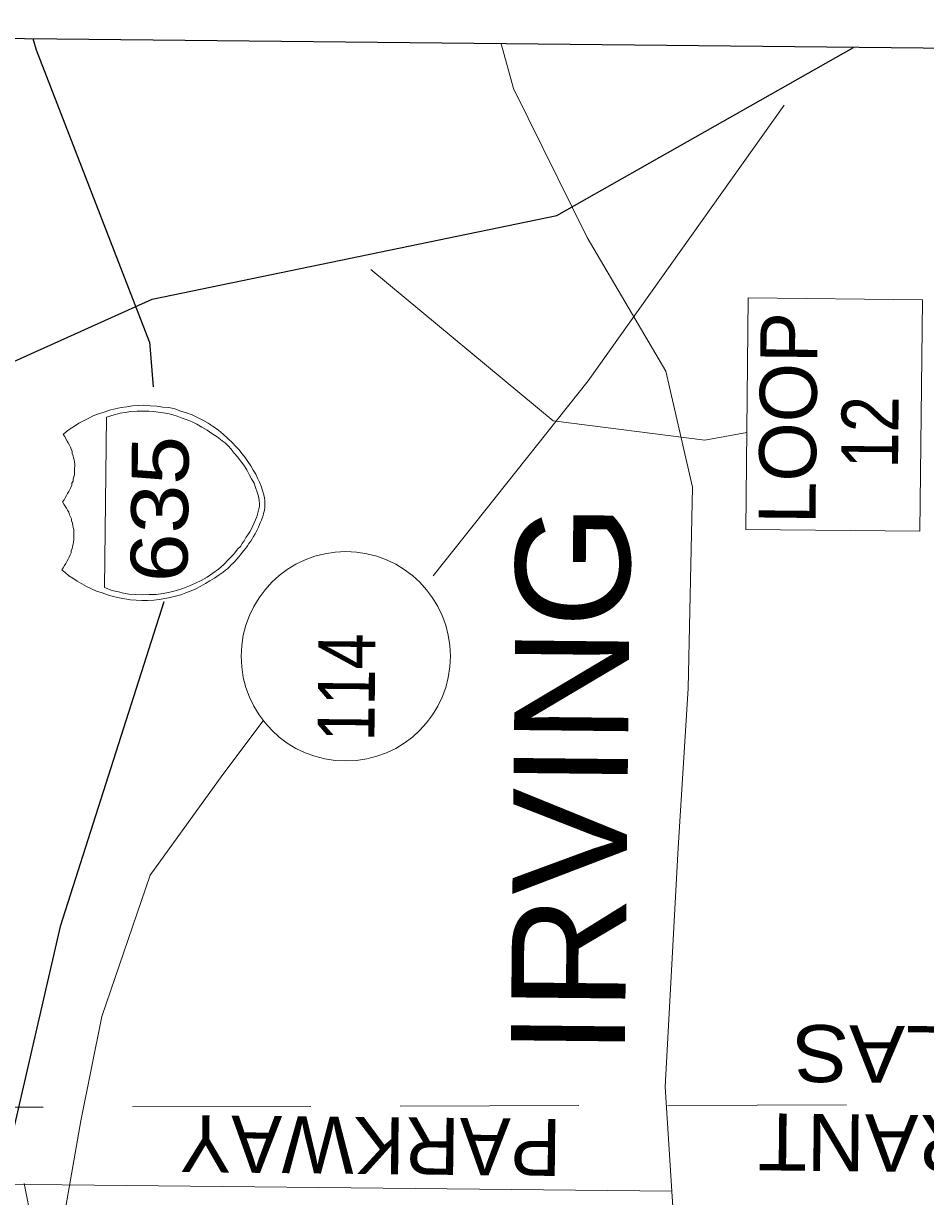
# Model space of a CAD drawing. Extents: x 2356576 to 2377878, y 6966390 to 6990634.
# Drawn here: x 2365779.3 to 2365886.9, y 6969120 to 6969259.9 of the extents above; entities that cross this region are included whole.
import ezdxf

# ---------------------------------------------------------------- set-up
doc = ezdxf.new("R2010")
doc.units = 0
doc.header["$LTSCALE"] = 7.1
doc.linetypes.add('MEDIUM_DASHED', pattern=[4.5, 3, -1.5])
doc.layers.add('19', color=7, linetype='Continuous', lineweight=13)
doc.layers.add('8', color=7, linetype='Continuous', lineweight=13)

msp = doc.modelspace()

# ---------------------------------------------------------------- linework, layer by layer
at = {"layer": '19'}
for p, q in [((2365846.673, 6969217.286), (2365870.055, 6969250.17)), ((2365846.673, 6969217.286), (2365828.192, 6969194.045)), ((2365860.613, 6969210.214), (2365865.603, 6969211.122)), ((2365803.105, 6969170.335), (2365807.911, 6969176.734)), ((2365856.653, 6969120.666), (2365765.574, 6969121.609)), ((2365782.284, 6969107.031), (2365779.407, 6969121.586))]:
    msp.add_line(p, q, dxfattribs=at)
at = {"layer": '19', "lineweight": 25}
msp.add_line((2365794.367, 6969221.94), (2365794.791, 6969216.564), dxfattribs=at)
at = {"layer": '19', "linetype": 'MEDIUM_DASHED'}
msp.add_line((2365728.404, 6969130.515), (2366103.06, 6969131.614), dxfattribs=at)
at = {"layer": '19', "lineweight": 25}
for points in [[(2365597.072, 6968660.498), (2366217.375, 6968654.072), (2366223.585, 6969253.468), (2365603.282, 6969259.894)], [(2365794.367, 6969221.94), (2365780.866, 6969256.702), (2365780.488, 6969258.058)], [(2365768.042, 6969215.073), (2365794.66, 6969227.038), (2365842.946, 6969237.006), (2365878.319, 6969257.045)], [(2365796.054, 6969190.929), (2365783.684, 6969152.235), (2365776.613, 6969121.495)]]:
    msp.add_lwpolyline(points, dxfattribs=at)
at = {"layer": '19'}
for points in [[(2365858.767, 6969084.158), (2365857.839, 6969101.96), (2365855.882, 6969133.094), (2365857.437, 6969161.612), (2365858.594, 6969180.589), (2365859.115, 6969204.617), (2365855.958, 6969218.422), (2365846.578, 6969234.36), (2365837.794, 6969252.124), (2365836.317, 6969257.48)], [(2365860.613, 6969210.214), (2365842.512, 6969212.529), (2365820.77, 6969230.575)], [(2365784.579, 6969203.829), (2365784.729, 6969204.067), (2365784.852, 6969204.338), (2365784.946, 6969204.545), (2365785.069, 6969204.844), (2365785.1, 6969205.084), (2365785.222, 6969205.322), (2365785.257, 6969205.562), (2365785.32, 6969205.833), (2365785.382, 6969206.073), (2365785.413, 6969206.34), (2365785.415, 6969206.58), (2365785.418, 6969206.852), (2365785.421, 6969207.092), (2365785.423, 6969207.36), (2365785.398, 6969207.633), (2365785.341, 6969207.873), (2365785.283, 6969208.082), (2365785.254, 6969208.354), (2365785.136, 6969208.623), (2365785.111, 6969208.864), (2365784.994, 6969209.137), (2365784.904, 6969209.378), (2365784.787, 6969209.619), (2365784.642, 6969209.889), (2365784.524, 6969210.102), (2365784.375, 6969210.371), (2365784.229, 6969210.645), (2365784.052, 6969210.887), (2365784.444, 6969211.243), (2365784.899, 6969211.566), (2365785.382, 6969211.893), (2365785.926, 6969212.215), (2365786.469, 6969212.51), (2365787.04, 6969212.804), (2365787.643, 6969213.098), (2365788.245, 6969213.331), (2365788.94, 6969213.564), (2365789.57, 6969213.77), (2365790.264, 6969213.943), (2365790.953, 6969214.083), (2365791.647, 6969214.196), (2365792.336, 6969214.309), (2365792.996, 6969214.334), (2365793.689, 6969214.387), (2365794.436, 6969214.319), (2365795.216, 6969214.279), (2365795.934, 6969214.152), (2365796.654, 6969214.084), (2365797.372, 6969213.929), (2365798.09, 6969213.681), (2365798.747, 6969213.463), (2365799.437, 6969213.215), (2365800.094, 6969212.909), (2365800.718, 6969212.574), (2365801.347, 6969212.236), (2365801.943, 6969211.841), (2365802.566, 6969211.383), (2365803.133, 6969210.929), (2365803.668, 6969210.443), (2365804.235, 6969209.898), (2365804.619, 6969209.502), (2365805.006, 6969209.078), (2365805.389, 6969208.594), (2365805.745, 6969208.142), (2365806.072, 6969207.658), (2365806.426, 6969207.143), (2365806.721, 6969206.632), (2365807.016, 6969206.149), (2365807.251, 6969205.694), (2365807.486, 6969205.184), (2365807.689, 6969204.702), (2365807.836, 6969204.22), (2365807.952, 6969203.799), (2365808.067, 6969203.378), (2365808.123, 6969202.957), (2365808.119, 6969202.597)], [(2365808.119, 6969202.597), (2365808.117, 6969202.357), (2365808.115, 6969202.145), (2365808.052, 6969201.906), (2365808.018, 6969201.698), (2365807.955, 6969201.459), (2365807.893, 6969201.219), (2365807.802, 6969200.92), (2365807.707, 6969200.649), (2365807.585, 6969200.41), (2365807.462, 6969200.144), (2365807.339, 6969199.845), (2365807.216, 6969199.574), (2365807.065, 6969199.276), (2365806.942, 6969199.037), (2365806.759, 6969198.739), (2365806.604, 6969198.44), (2365806.421, 6969198.174), (2365806.21, 6969197.876), (2365806.027, 6969197.606), (2365805.845, 6969197.34), (2365805.63, 6969197.07), (2365805.387, 6969196.805), (2365805.204, 6969196.535), (2365804.994, 6969196.297), (2365804.779, 6969196.031), (2365804.569, 6969195.793), (2365804.326, 6969195.552), (2365804.084, 6969195.346), (2365803.869, 6969195.077), (2365803.659, 6969194.871), (2365803.417, 6969194.721), (2365803.143, 6969194.484), (2365802.659, 6969194.129), (2365802.115, 6969193.747), (2365801.54, 6969193.421), (2365801.028, 6969193.098), (2365800.453, 6969192.804), (2365799.882, 6969192.478), (2365799.308, 6969192.244), (2365798.677, 6969192.01), (2365798.075, 6969191.776), (2365797.441, 6969191.603), (2365796.811, 6969191.461), (2365796.178, 6969191.316), (2365795.517, 6969191.203), (2365794.856, 6969191.122), (2365794.135, 6969191.069), (2365793.447, 6969191.076), (2365792.755, 6969191.111), (2365792.096, 6969191.178), (2365791.409, 6969191.277), (2365790.718, 6969191.405), (2365790.032, 6969191.56), (2365789.342, 6969191.747), (2365788.716, 6969191.993), (2365788.027, 6969192.213), (2365787.429, 6969192.487), (2365786.832, 6969192.765), (2365786.267, 6969193.071), (2365785.731, 6969193.376), (2365785.194, 6969193.742), (2365784.717, 6969194.047), (2365784.269, 6969194.412), (2365783.885, 6969194.744), (2365784.067, 6969194.982), (2365784.218, 6969195.28), (2365784.373, 6969195.519), (2365784.495, 6969195.757), (2365784.646, 6969196.028), (2365784.768, 6969196.266), (2365784.863, 6969196.538), (2365784.986, 6969196.776), (2365785.016, 6969197.016), (2365785.139, 6969197.283), (2365785.173, 6969197.522), (2365785.236, 6969197.794), (2365785.299, 6969198.061), (2365785.329, 6969198.273), (2365785.332, 6969198.513), (2365785.335, 6969198.813), (2365785.337, 6969199.053), (2365785.34, 6969199.293), (2365785.315, 6969199.561), (2365785.257, 6969199.802), (2365785.2, 6969200.042), (2365785.17, 6969200.315), (2365785.053, 6969200.584), (2365785.028, 6969200.824), (2365784.91, 6969201.065), (2365784.821, 6969201.306), (2365784.704, 6969201.607), (2365784.558, 6969201.849), (2365784.441, 6969202.09), (2365784.291, 6969202.332), (2365784.146, 6969202.573), (2365783.969, 6969202.847), (2365784.151, 6969203.085), (2365784.302, 6969203.324), (2365784.456, 6969203.59), (2365784.579, 6969203.829)], [(2365786.172, 6969129.044), (2365788.641, 6969141.499), (2365794.428, 6969158.332), (2365803.105, 6969170.335)], [(2365786.237, 6969088.99), (2365782.284, 6969107.031), (2365786.172, 6969129.044)]]:
    msp.add_lwpolyline(points, dxfattribs=at)
for points in [[(2365865.483, 6969199.571), (2365886.27, 6969199.355), (2365886.556, 6969226.954), (2365865.769, 6969227.169)], [(2365789.201, 6969212.933), (2365788.991, 6969192.623), (2365789.29, 6969192.499), (2365789.648, 6969192.376), (2365790.067, 6969192.251), (2365790.638, 6969192.125), (2365791.236, 6969191.967), (2365791.895, 6969191.84), (2365792.643, 6969191.805), (2365793.454, 6969191.764), (2365794.295, 6969191.788), (2365795.135, 6969191.807), (2365795.976, 6969191.918), (2365796.786, 6969192.09), (2365797.568, 6969192.294), (2365798.322, 6969192.526), (2365799.105, 6969192.818), (2365799.829, 6969193.138), (2365800.521, 6969193.491), (2365801.245, 6969193.876), (2365801.909, 6969194.349), (2365802.578, 6969194.822), (2365803.212, 6969195.383), (2365803.79, 6969195.981), (2365804.365, 6969196.576), (2365804.883, 6969197.23), (2365805.187, 6969197.527), (2365805.398, 6969197.885), (2365805.642, 6969198.21), (2365805.858, 6969198.6), (2365806.069, 6969198.926), (2365806.313, 6969199.283), (2365806.497, 6969199.642), (2365806.68, 6969200), (2365806.836, 6969200.358), (2365806.987, 6969200.689), (2365807.143, 6969201.047), (2365807.235, 6969201.374), (2365807.33, 6969201.705), (2365807.393, 6969202.004), (2365807.456, 6969202.304), (2365807.459, 6969202.604), (2365807.432, 6969203.024), (2365807.349, 6969203.533), (2365807.202, 6969204.015), (2365806.999, 6969204.557), (2365806.825, 6969205.07), (2365806.53, 6969205.614), (2365806.236, 6969206.125), (2365805.941, 6969206.668), (2365805.587, 6969207.211), (2365805.2, 6969207.727), (2365804.845, 6969208.211), (2365804.462, 6969208.663), (2365804.107, 6969209.119), (2365803.719, 6969209.511), (2365803.362, 6969209.875), (2365803.005, 6969210.118), (2365802.41, 6969210.605), (2365801.782, 6969211.003), (2365801.218, 6969211.397), (2365800.59, 6969211.763), (2365799.993, 6969212.102), (2365799.428, 6969212.376), (2365798.859, 6969212.621), (2365798.261, 6969212.84), (2365797.663, 6969213.054), (2365797.125, 6969213.239), (2365796.526, 6969213.366), (2365795.959, 6969213.463), (2365795.388, 6969213.557), (2365794.821, 6969213.623), (2365794.249, 6969213.661), (2365793.681, 6969213.667), (2365792.869, 6969213.676), (2365792.121, 6969213.623), (2365791.459, 6969213.51), (2365790.858, 6969213.424), (2365790.285, 6969213.282), (2365789.863, 6969213.135), (2365789.502, 6969213.018)]]:
    msp.add_lwpolyline(points, close=True, dxfattribs=at)
msp.add_circle((2365817.767, 6969184.436), 12.486, dxfattribs=at)
at = {"layer": '8'}
for p, q in [((2365846.673, 6969217.286), (2365870.055, 6969250.17)), ((2365846.673, 6969217.286), (2365828.192, 6969194.045)), ((2365860.613, 6969210.214), (2365865.603, 6969211.122)), ((2365803.105, 6969170.335), (2365807.911, 6969176.734)), ((2365856.653, 6969120.666), (2365765.574, 6969121.609)), ((2365782.284, 6969107.031), (2365779.407, 6969121.586))]:
    msp.add_line(p, q, dxfattribs=at)
at = {"layer": '8', "lineweight": 25}
msp.add_line((2365794.367, 6969221.94), (2365794.791, 6969216.564), dxfattribs=at)
at = {"layer": '8', "linetype": 'MEDIUM_DASHED'}
msp.add_line((2365728.404, 6969130.515), (2366103.06, 6969131.614), dxfattribs=at)
at = {"layer": '8', "lineweight": 25}
for points in [[(2365597.072, 6968660.498), (2366217.375, 6968654.072), (2366223.585, 6969253.468), (2365603.282, 6969259.894)], [(2365794.367, 6969221.94), (2365780.866, 6969256.702), (2365780.488, 6969258.058)], [(2365768.042, 6969215.073), (2365794.66, 6969227.038), (2365842.946, 6969237.006), (2365878.319, 6969257.045)], [(2365796.054, 6969190.929), (2365783.684, 6969152.235), (2365776.613, 6969121.495)]]:
    msp.add_lwpolyline(points, dxfattribs=at)
at = {"layer": '8'}
for points in [[(2365858.767, 6969084.158), (2365857.839, 6969101.96), (2365855.882, 6969133.094), (2365857.437, 6969161.612), (2365858.594, 6969180.589), (2365859.115, 6969204.617), (2365855.958, 6969218.422), (2365846.578, 6969234.36), (2365837.794, 6969252.124), (2365836.317, 6969257.48)], [(2365860.613, 6969210.214), (2365842.512, 6969212.529), (2365820.77, 6969230.575)], [(2365784.579, 6969203.829), (2365784.729, 6969204.067), (2365784.852, 6969204.338), (2365784.946, 6969204.545), (2365785.069, 6969204.844), (2365785.1, 6969205.084), (2365785.222, 6969205.322), (2365785.257, 6969205.562), (2365785.32, 6969205.833), (2365785.382, 6969206.073), (2365785.413, 6969206.34), (2365785.415, 6969206.58), (2365785.418, 6969206.852), (2365785.421, 6969207.092), (2365785.423, 6969207.36), (2365785.398, 6969207.633), (2365785.341, 6969207.873), (2365785.283, 6969208.082), (2365785.254, 6969208.354), (2365785.136, 6969208.623), (2365785.111, 6969208.864), (2365784.994, 6969209.137), (2365784.904, 6969209.378), (2365784.787, 6969209.619), (2365784.642, 6969209.889), (2365784.524, 6969210.102), (2365784.375, 6969210.371), (2365784.229, 6969210.645), (2365784.052, 6969210.887), (2365784.444, 6969211.243), (2365784.899, 6969211.566), (2365785.382, 6969211.893), (2365785.926, 6969212.215), (2365786.469, 6969212.51), (2365787.04, 6969212.804), (2365787.643, 6969213.098), (2365788.245, 6969213.331), (2365788.94, 6969213.564), (2365789.57, 6969213.77), (2365790.264, 6969213.943), (2365790.953, 6969214.083), (2365791.647, 6969214.196), (2365792.336, 6969214.309), (2365792.996, 6969214.334), (2365793.689, 6969214.387), (2365794.436, 6969214.319), (2365795.216, 6969214.279), (2365795.934, 6969214.152), (2365796.654, 6969214.084), (2365797.372, 6969213.929), (2365798.09, 6969213.681), (2365798.747, 6969213.463), (2365799.437, 6969213.215), (2365800.094, 6969212.909), (2365800.718, 6969212.574), (2365801.347, 6969212.236), (2365801.943, 6969211.841), (2365802.566, 6969211.383), (2365803.133, 6969210.929), (2365803.668, 6969210.443), (2365804.235, 6969209.898), (2365804.619, 6969209.502), (2365805.006, 6969209.078), (2365805.389, 6969208.594), (2365805.745, 6969208.142), (2365806.072, 6969207.658), (2365806.426, 6969207.143), (2365806.721, 6969206.632), (2365807.016, 6969206.149), (2365807.251, 6969205.694), (2365807.486, 6969205.184), (2365807.689, 6969204.702), (2365807.836, 6969204.22), (2365807.952, 6969203.799), (2365808.067, 6969203.378), (2365808.123, 6969202.957), (2365808.119, 6969202.597)], [(2365808.119, 6969202.597), (2365808.117, 6969202.357), (2365808.115, 6969202.145), (2365808.052, 6969201.906), (2365808.018, 6969201.698), (2365807.955, 6969201.459), (2365807.893, 6969201.219), (2365807.802, 6969200.92), (2365807.707, 6969200.649), (2365807.585, 6969200.41), (2365807.462, 6969200.144), (2365807.339, 6969199.845), (2365807.216, 6969199.574), (2365807.065, 6969199.276), (2365806.942, 6969199.037), (2365806.759, 6969198.739), (2365806.604, 6969198.44), (2365806.421, 6969198.174), (2365806.21, 6969197.876), (2365806.027, 6969197.606), (2365805.845, 6969197.34), (2365805.63, 6969197.07), (2365805.387, 6969196.805), (2365805.204, 6969196.535), (2365804.994, 6969196.297), (2365804.779, 6969196.031), (2365804.569, 6969195.793), (2365804.326, 6969195.552), (2365804.084, 6969195.346), (2365803.869, 6969195.077), (2365803.659, 6969194.871), (2365803.417, 6969194.721), (2365803.143, 6969194.484), (2365802.659, 6969194.129), (2365802.115, 6969193.747), (2365801.54, 6969193.421), (2365801.028, 6969193.098), (2365800.453, 6969192.804), (2365799.882, 6969192.478), (2365799.308, 6969192.244), (2365798.677, 6969192.01), (2365798.075, 6969191.776), (2365797.441, 6969191.603), (2365796.811, 6969191.461), (2365796.178, 6969191.316), (2365795.517, 6969191.203), (2365794.856, 6969191.122), (2365794.135, 6969191.069), (2365793.447, 6969191.076), (2365792.755, 6969191.111), (2365792.096, 6969191.178), (2365791.409, 6969191.277), (2365790.718, 6969191.405), (2365790.032, 6969191.56), (2365789.342, 6969191.747), (2365788.716, 6969191.993), (2365788.027, 6969192.213), (2365787.429, 6969192.487), (2365786.832, 6969192.765), (2365786.267, 6969193.071), (2365785.731, 6969193.376), (2365785.194, 6969193.742), (2365784.717, 6969194.047), (2365784.269, 6969194.412), (2365783.885, 6969194.744), (2365784.067, 6969194.982), (2365784.218, 6969195.28), (2365784.373, 6969195.519), (2365784.495, 6969195.757), (2365784.646, 6969196.028), (2365784.768, 6969196.266), (2365784.863, 6969196.538), (2365784.986, 6969196.776), (2365785.016, 6969197.016), (2365785.139, 6969197.283), (2365785.173, 6969197.522), (2365785.236, 6969197.794), (2365785.299, 6969198.061), (2365785.329, 6969198.273), (2365785.332, 6969198.513), (2365785.335, 6969198.813), (2365785.337, 6969199.053), (2365785.34, 6969199.293), (2365785.315, 6969199.561), (2365785.257, 6969199.802), (2365785.2, 6969200.042), (2365785.17, 6969200.315), (2365785.053, 6969200.584), (2365785.028, 6969200.824), (2365784.91, 6969201.065), (2365784.821, 6969201.306), (2365784.704, 6969201.607), (2365784.558, 6969201.849), (2365784.441, 6969202.09), (2365784.291, 6969202.332), (2365784.146, 6969202.573), (2365783.969, 6969202.847), (2365784.151, 6969203.085), (2365784.302, 6969203.324), (2365784.456, 6969203.59), (2365784.579, 6969203.829)], [(2365786.172, 6969129.044), (2365788.641, 6969141.499), (2365794.428, 6969158.332), (2365803.105, 6969170.335)], [(2365786.237, 6969088.99), (2365782.284, 6969107.031), (2365786.172, 6969129.044)]]:
    msp.add_lwpolyline(points, dxfattribs=at)
for points in [[(2365865.483, 6969199.571), (2365886.27, 6969199.355), (2365886.556, 6969226.954), (2365865.769, 6969227.169)], [(2365789.201, 6969212.933), (2365788.991, 6969192.623), (2365789.29, 6969192.499), (2365789.648, 6969192.376), (2365790.067, 6969192.251), (2365790.638, 6969192.125), (2365791.236, 6969191.967), (2365791.895, 6969191.84), (2365792.643, 6969191.805), (2365793.454, 6969191.764), (2365794.295, 6969191.788), (2365795.135, 6969191.807), (2365795.976, 6969191.918), (2365796.786, 6969192.09), (2365797.568, 6969192.294), (2365798.322, 6969192.526), (2365799.105, 6969192.818), (2365799.829, 6969193.138), (2365800.521, 6969193.491), (2365801.245, 6969193.876), (2365801.909, 6969194.349), (2365802.578, 6969194.822), (2365803.212, 6969195.383), (2365803.79, 6969195.981), (2365804.365, 6969196.576), (2365804.883, 6969197.23), (2365805.187, 6969197.527), (2365805.398, 6969197.885), (2365805.642, 6969198.21), (2365805.858, 6969198.6), (2365806.069, 6969198.926), (2365806.313, 6969199.283), (2365806.497, 6969199.642), (2365806.68, 6969200), (2365806.836, 6969200.358), (2365806.987, 6969200.689), (2365807.143, 6969201.047), (2365807.235, 6969201.374), (2365807.33, 6969201.705), (2365807.393, 6969202.004), (2365807.456, 6969202.304), (2365807.459, 6969202.604), (2365807.432, 6969203.024), (2365807.349, 6969203.533), (2365807.202, 6969204.015), (2365806.999, 6969204.557), (2365806.825, 6969205.07), (2365806.53, 6969205.614), (2365806.236, 6969206.125), (2365805.941, 6969206.668), (2365805.587, 6969207.211), (2365805.2, 6969207.727), (2365804.845, 6969208.211), (2365804.462, 6969208.663), (2365804.107, 6969209.119), (2365803.719, 6969209.511), (2365803.362, 6969209.875), (2365803.005, 6969210.118), (2365802.41, 6969210.605), (2365801.782, 6969211.003), (2365801.218, 6969211.397), (2365800.59, 6969211.763), (2365799.993, 6969212.102), (2365799.428, 6969212.376), (2365798.859, 6969212.621), (2365798.261, 6969212.84), (2365797.663, 6969213.054), (2365797.125, 6969213.239), (2365796.526, 6969213.366), (2365795.959, 6969213.463), (2365795.388, 6969213.557), (2365794.821, 6969213.623), (2365794.249, 6969213.661), (2365793.681, 6969213.667), (2365792.869, 6969213.676), (2365792.121, 6969213.623), (2365791.459, 6969213.51), (2365790.858, 6969213.424), (2365790.285, 6969213.282), (2365789.863, 6969213.135), (2365789.502, 6969213.018)]]:
    msp.add_lwpolyline(points, close=True, dxfattribs=at)
msp.add_circle((2365817.767, 6969184.436), 12.486, dxfattribs=at)

# ---------------------------------------------------------------- texts
at = {"layer": '19'}
for s, rotation, p in [('LOOP', 89.406, (2365873.798, 6969200.176)), ('PARKWAY', 179.406, (2365843.509, 6969129.262))]:
    msp.add_text(s, height=6.798, rotation=rotation, dxfattribs=at).set_placement(p)
for s, height, rotation, width, p in [('12', 6.798, 89.406, 0.85, (2365883.647, 6969206.823)), ('635', 6.798, 89.406, 1.15, (2365798.87, 6969193.24)), ('IRVING', 13.62, 89.406, 1.05, (2365851.059, 6969136.745)), ('114', 6.798, 89.406, 0.85, (2365821.174, 6969174.256)), ('DALLAS', 6.798, 179.406, 1.1, (2365909.509, 6969140.099)), ('TARRANT', 6.798, 179.406, 1.05, (2365912.071, 6969129.48))]:
    msp.add_text(s, height=height, rotation=rotation, dxfattribs=dict(at, width=width)).set_placement(p)
at = {"layer": '8'}
for s, rotation, p in [('LOOP', 89.406, (2365873.798, 6969200.176)), ('PARKWAY', 179.406, (2365843.509, 6969129.262))]:
    msp.add_text(s, height=6.798, rotation=rotation, dxfattribs=at).set_placement(p)
for s, height, rotation, width, p in [('12', 6.798, 89.406, 0.85, (2365883.647, 6969206.823)), ('635', 6.798, 89.406, 1.15, (2365798.87, 6969193.24)), ('IRVING', 13.62, 89.406, 1.05, (2365851.059, 6969136.745)), ('114', 6.798, 89.406, 0.85, (2365821.174, 6969174.256)), ('DALLAS', 6.798, 179.406, 1.1, (2365909.509, 6969140.099)), ('TARRANT', 6.798, 179.406, 1.05, (2365912.071, 6969129.48))]:
    msp.add_text(s, height=height, rotation=rotation, dxfattribs=dict(at, width=width)).set_placement(p)

doc.saveas('drawing.dxf')
